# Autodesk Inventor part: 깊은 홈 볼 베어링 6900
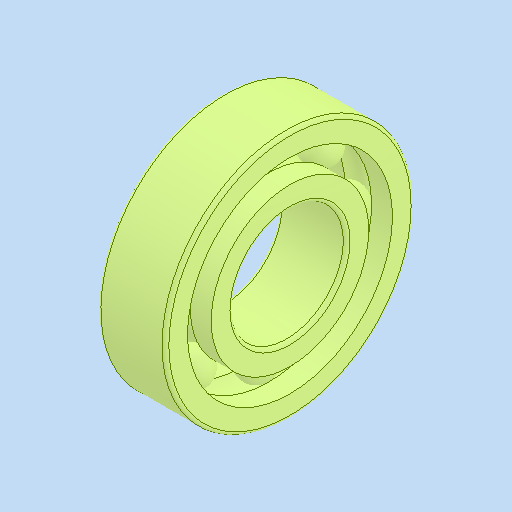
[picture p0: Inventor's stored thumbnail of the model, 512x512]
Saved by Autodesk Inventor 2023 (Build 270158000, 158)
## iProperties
Created: 2026-04
Part Number: 깊은 홈 볼 베어링 6900
Material: 강철, 연강
Description: 깊은 그루브 볼 베어링
Document SubType Name: Modeling
Designer: home
Density: 7.85 g/cm^3
Appearance: 기본값
Author: jhkim
Sending System: Autodesk Inventor 2027
Preprocessor: ST-DEVELOPER v20.1
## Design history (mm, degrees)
feature "Solid1"
feature "Solid1:1"
feature "Solid1:2"
feature "Solid1:3"
feature "Solid1:4"
feature "Solid1:5"
feature "Solid1:6"
feature "Solid1:7"
feature "Solid1:8"
feature "Solid1:9"
node "솔리드1"
node "솔리드2"
node "솔리드3"
node "솔리드4"
node "솔리드5"
node "솔리드6"
node "솔리드7"
node "솔리드8"
node "솔리드9"
node "솔리드10"
